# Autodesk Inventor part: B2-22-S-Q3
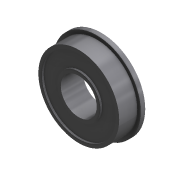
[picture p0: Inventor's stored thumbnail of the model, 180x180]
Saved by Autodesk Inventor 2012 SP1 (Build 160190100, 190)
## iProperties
Shininess: 0.0
Length Units: 11269
Angle Units: 11279
Time Units: 11290
Mass Units: 11283
Length Display Precision: 3
Angle Display Precision: 2
Compacted: True
Created: 2000-06
Part Number: B2-22-S-Q3
Description: FLANGED BEARING, .50 X 1.125
Vendor: WM BERG
Document SubType Name: Modeling
Designer: Ron
Density: 1 g/cm^3
Material: Default
Density: 0.0
Volumn: 0.0
Area: 0.0
PropertySet Name: Model Information
Control State: 0
Master: False
Checked Out: False
Title: FLANGE BEARING
Author: Ron
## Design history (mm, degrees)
node "RevolutionFull1" dims "d14" = 360 deg
  sketch "Sketch1"
    geometry: L1 (-7.62, 2.775)-(-7.62, 2.14); L2 (-7.62, 2.14)-(-13.018, 2.14); L3 (-13.018, 2.14)-(-13.018, 2.775); L4 (-14.288, 2.775)-(-13.018, 2.775); L5 (-14.287, -5.163)-(-14.288, 2.775); L6 (-13.018, -5.163)-(-14.287, -5.163); L7 (-13.018, -4.528)-(-13.018, -5.163); L8 (-7.62, -4.528)-(-13.018, -4.528); L9 (-7.62, -5.163)-(-7.62, -4.528); L10 (-6.35, -5.163)-(-7.62, -5.163); L11 (-6.35, 2.775)-(-6.35, -5.163); L12 (-7.62, 2.775)-(-6.35, 2.775); L13 (0, -5.808)-(0, 6.309); L14 (0, -5.808)-(0, 6.309)
    constraints: 28 end point, 7 vertical, 6 horizontal, 4 collinear, 1 other
    dimensions: "d1" = 12.7 diameter of L10.start L13 (computed from id); "d3" = 28.575 diameter of L5.start L13 (computed from od); "d5" = 7.9375 distance of L5.start L4.start (computed from w); "d7" = 1.27 distance of L10.start L9.start; "d9" = 1.27 distance of L6.start L5.start; "d11" = 0.635 vertical distance of L7.start L5.start; "d13" = 0.635 vertical distance of L2.end L4.start
node "WorkAxis1"
node "WorkPlane1"
node "RevolutionFull2" dims "d18" = 360 deg
  sketch "Sketch2"
    geometry: L1 (-14.288, -2.394)-(-14.288, -3.969); L2 (-15.558, -2.394)-(-14.288, -2.394); L3 (-15.558, -3.969)-(-15.558, -2.394); L4 (-14.288, -3.969)-(-15.558, -3.969); L5 (-14.287, -3.969)-(-14.287, 3.969) reference; L6 (14.288, -3.969)-(-14.287, -3.969) reference; L7 (0, 20.592)-(0, -20.592)
    constraints: 10 end point, 2 collinear, 2 horizontal, 2 vertical
    dimensions: "d17" = 1.5748 distance of L3.start L2.start (computed from flt)
body "Solid1"
other parameters: "id" = 127 [user parameter; used in 1 equation term], "od" = 285.75 [user parameter; used in 1 equation term], "w" = 79.375 [user parameter; used in 1 equation term], "flgod" = 311.15 [user parameter], "flt" = 15.748 [user parameter; used in 1 equation term], "d0" = 12.7 (derived), "d2" = 28.575 (derived), "d4" = 7.9375 (derived), "d6" = 1.27 (derived), "d8" = 1.27 (derived), "d10" = 0.635 (derived), "d12" = 0.635 (derived), "d15" = 0, "d16" = 1.5748 (derived)
